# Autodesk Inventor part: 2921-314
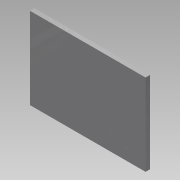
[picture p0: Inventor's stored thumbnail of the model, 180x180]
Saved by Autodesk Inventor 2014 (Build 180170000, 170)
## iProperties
Company: NHTSA/VRTC
Created: 2013-12
Part Number: 2921-314
Project: CHILD SIDE IMPACT SLED
Material: Steel, Mild
Description: BENCH FRAME CENTER STIFFENER PLATE
Document SubType Name: Modeling
Designer: Dave Walker
Stock Number: PL9.5 (3/8") x 172-3 (6 13/16") x 243.9 (9 5/8")
Mass: 3143.81 g
Surface Area: 919.101 cm^2
Volume: 399.975 cm^3
Density: 7.86 g/cm^3
Appearance: Steel
Title: Bench Frame Center Stiffener Plate
Subject: Child Side Impact Sled
Author: Dave Walker
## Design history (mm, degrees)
sketch "Sketch1"
  geometry: L1 (-243.9, 86.106)-(0, 86.106); L2 (0, 86.106)-(0, -86.106); L3 (0, -86.106)-(-243.9, -86.106); L4 (-243.9, -86.106)-(-243.9, 86.106); 2 further points
  constraints: 8 end point, 2 parallel, 1 coincident, 1 horizontal, 1 midpoint, 1 perpendicular
  dimensions: "d0" = 172.212 distance of L3.end L1.start; "d1" = 243.9 distance of L1.start L1.end
extrude "Extrusion1" new body sketch "Sketch1" distance "d2" = 9.525; taper "d3" = 0 deg
body "Solid1"
